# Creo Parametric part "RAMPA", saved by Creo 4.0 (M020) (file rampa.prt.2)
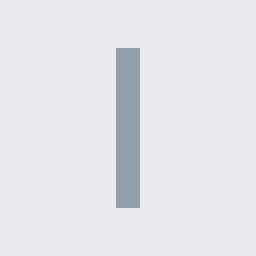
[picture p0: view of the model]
Units: millimeter Newton Second (mmNs); MM, TONNE, SECS

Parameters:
  MODELED_BY = "AJ"

Created from: MMNS_PART_SOLID.PRT

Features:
  1. datum plane "RIGHT"
  2. datum plane "TOP"
  3. datum plane "FRONT"
  4. coordinate system
  5. extrusion "Extrusión 1"
  6. datum axis "A_1"

Surfaces: 6 plane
